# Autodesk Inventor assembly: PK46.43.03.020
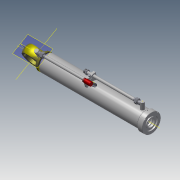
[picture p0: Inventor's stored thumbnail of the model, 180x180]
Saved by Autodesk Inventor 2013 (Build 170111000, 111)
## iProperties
Shininess: 64.0
Length Units: 11269
Angle Units: 11279
Time Units: 11290
Mass Units: 11283
Length Display Precision: 3
Angle Display Precision: 2
Compacted: True
Created: 2004-11
Part Number: PK46.43.03.020
Document SubType Name: Assembly
Designer: ELarisa
Manufacturer: Standard
Standards Organization: Custom
Mass: 67108 g
Surface Area: 14253.4 cm^2
Volume: 8553.82 cm^3
Density: 7.84538 g/cm^3
Density: 0.0
Volumn: 0.0
Area: 0.0
PropertySet Name: Model Information
Control State: 0
Master: False
Checked Out: False
Author: ELarisa
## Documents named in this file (13)
- D:\FrontLoaderVault\Data\Assy, Chassis, Front\PK46.43.03.020.iam
- D:\FrontLoaderVault\Data\Assy, Chassis, Front\PK46.43.01.002.ipt
- D:\FrontLoaderVault\Data\Assy, Chassis, Front\PK46.43.01.007.ipt
- D:\FrontLoaderVault\Data\Assy, Chassis, Front\PK46.43.01.050.iam
- D:\FrontLoaderVault\Data\Assy, Chassis, Front\PK46.43.01.030.iam
- D:\FrontLoaderVault\Data\Assy, Chassis, Front\PK46.43.01.006.ipt
- D:\FrontLoaderVault\Data\Assy, Chassis, Front\PK46.43.01.040.iam
- D:\FrontLoaderVault\Data\Assy, Chassis, Front\PK46.43.01.015.ipt
- D:\FrontLoaderVault\Data\Assy, Chassis, Front\PK46.43.01.016.ipt
- D:\FrontLoaderVault\Data\Assy, Chassis, Front\PK46.43.01.004.ipt
- D:\FrontLoaderVault\Data\Assy, Chassis, Front\PK46.43.01.005.ipt
- D:\FrontLoaderVault\Data\Assy, Chassis, Front\12.65G.019.ipt
- D:\FrontLoaderVault\Data\Assy, Chassis, Front\M12-6gx45.58.019(S18).ipt
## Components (13 placed, 12 different names)
1. PK46.43.01.002:1 — Insert:7, Insert:9, Angle:7, Insert:32, Insert:23
2. PK46.43.01.030:1 [sub-assembly] — Angle:7, Insert:21, Angle:12, Angle:13, Insert:25
3. PK46.43.01.040:1 [sub-assembly] — Insert:21
4. PK46.43.01.007:1 — Insert:7, Insert:25
5. PK46.43.01.006:1 — Insert:11
6. PK46.43.01.004:1 — Insert:9, Insert:10
7. PK46.43.01.005:1 — Insert:10, Insert:11, Angle:11
8. PK46.43.01.030:2 [sub-assembly] — Angle:11, Angle:12, Insert:29, Insert:23
9. PK46.43.01.050:1 [sub-assembly] — Insert:29
10. PK46.43.01.015:1 — Insert:32, Angle:13, Flush:1, Angle:14, Mate:2, Mate:3
11. PK46.43.01.016:1 — Flush:1, Angle:14, Mate:2, Mate:3, Insert:33
12. 12.65G.019:1 — Insert:33, Insert:34
13. M12-6gx45.58.019(S18):1 — Insert:34
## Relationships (19: Insert 11, Angle 5, Mate 2, Flush 1)
- Insert:7: PK46.43.01.002:1 ↔ PK46.43.01.007:1
- Insert:9: PK46.43.01.002:1 ↔ PK46.43.01.004:1
- Insert:10: PK46.43.01.004:1 ↔ PK46.43.01.005:1
- Insert:11: PK46.43.01.006:1 ↔ PK46.43.01.005:1
- Angle:7: PK46.43.01.002:1 ↔ PK46.43.01.030:1
- Insert:21: PK46.43.01.030:1 ↔ PK46.43.01.040:1
- Angle:11: PK46.43.01.005:1 ↔ PK46.43.01.030:2
- Angle:12: PK46.43.01.030:1 ↔ PK46.43.01.030:2
- Insert:29: PK46.43.01.030:2 ↔ PK46.43.01.050:1
- Insert:32: PK46.43.01.002:1 ↔ PK46.43.01.015:1
- Angle:13: PK46.43.01.030:1 ↔ PK46.43.01.015:1
- Flush:1: PK46.43.01.015:1 ↔ PK46.43.01.016:1
- Angle:14: PK46.43.01.015:1 ↔ PK46.43.01.016:1
- Mate:2: PK46.43.01.015:1 ↔ PK46.43.01.016:1
- Mate:3: PK46.43.01.015:1 ↔ PK46.43.01.016:1
- Insert:33: PK46.43.01.016:1 ↔ 12.65G.019:1
- Insert:34: 12.65G.019:1 ↔ M12-6gx45.58.019(S18):1
- Insert:23: PK46.43.01.002:1 ↔ PK46.43.01.030:2
- Insert:25: PK46.43.01.030:1 ↔ PK46.43.01.007:1
